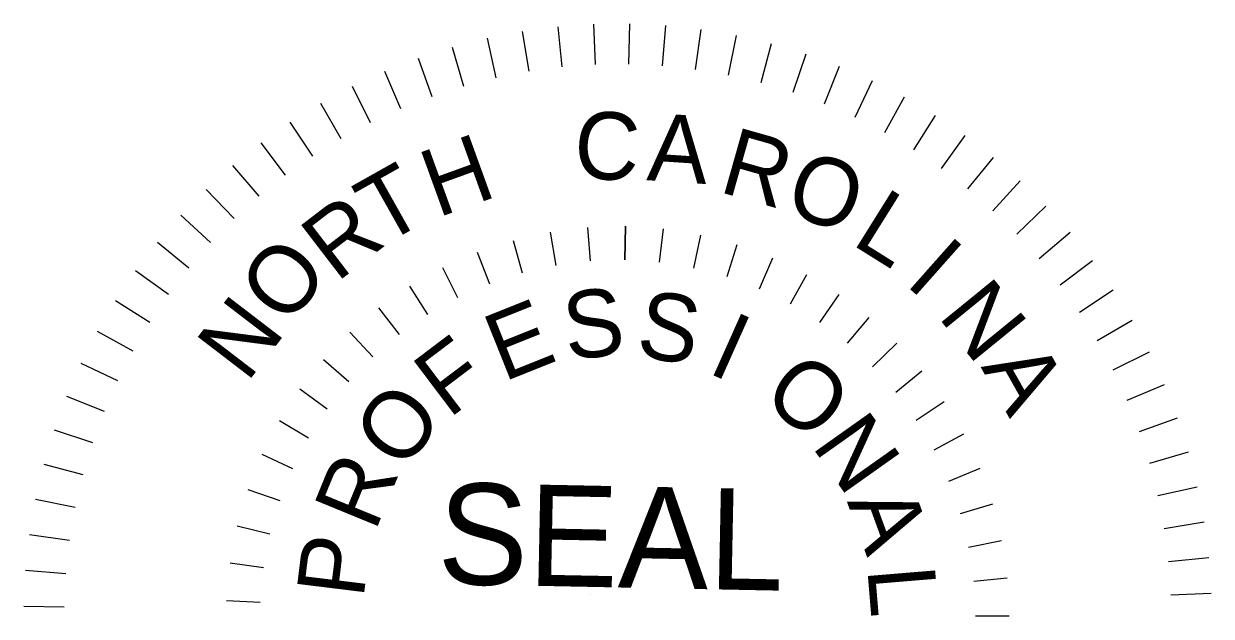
# Model space of a CAD drawing. Extents: x 0 to 2694, y -754 to 1499.
# Drawn here: x 3.6853 to 3.807, y 1.6046 to 1.6653 of the extents above; entities that cross this region are included whole.
import ezdxf

# ---------------------------------------------------------------- set-up
doc = ezdxf.new("R2010")
doc.units = 0
doc.layers.add('UBO Plan Sheet 34 CELL', color=7, linetype='Continuous')

msp = doc.modelspace()

# ---------------------------------------------------------------- linework, layer by layer
at = {"layer": 'UBO Plan Sheet 34 CELL'}
for p, q in [((3.73639, 1.66449), (3.73706, 1.6604)), ((3.74004, 1.66497), (3.74045, 1.66085)), ((3.7437, 1.66523), (3.74387, 1.66109)), ((3.74738, 1.66527), (3.7473, 1.66112)), ((3.75106, 1.66508), (3.75073, 1.66095)), ((3.75471, 1.66468), (3.75413, 1.66057)), ((3.73279, 1.66379), (3.73369, 1.65974)), ((3.75833, 1.66406), (3.7575, 1.65999)), ((3.72922, 1.66288), (3.73037, 1.65888)), ((3.76191, 1.66322), (3.76084, 1.65921)), ((3.76544, 1.66216), (3.76412, 1.65822)), ((3.72572, 1.66175), (3.72712, 1.65783)), ((3.76888, 1.66089), (3.76733, 1.65704)), ((3.7223, 1.6604), (3.72392, 1.65659)), ((3.71896, 1.65886), (3.72082, 1.65515)), ((3.77225, 1.65941), (3.77048, 1.65566)), ((3.77552, 1.65774), (3.77352, 1.6541)), ((3.71572, 1.65712), (3.7178, 1.65353)), ((3.7126, 1.65518), (3.71489, 1.65172)), ((3.77869, 1.65587), (3.77647, 1.65236)), ((3.78174, 1.65381), (3.77931, 1.65045)), ((3.7096, 1.65306), (3.71209, 1.64975)), ((3.78465, 1.65158), (3.78203, 1.64836)), ((3.70672, 1.65076), (3.70941, 1.64761)), ((3.78743, 1.64916), (3.78462, 1.64612)), ((3.704, 1.6483), (3.70687, 1.64531)), ((3.79006, 1.64659), (3.78707, 1.64372)), ((3.70143, 1.64567), (3.70447, 1.64286)), ((3.73925, 1.64393), (3.73984, 1.64052)), ((3.74309, 1.64441), (3.74336, 1.64097)), ((3.74697, 1.64452), (3.7469, 1.64107)), ((3.7469, 1.64107), (3.74697, 1.64452)), ((3.75084, 1.64426), (3.75044, 1.64083)), ((3.79252, 1.64387), (3.78937, 1.64118)), ((3.69901, 1.64289), (3.70223, 1.64027)), ((3.73547, 1.64308), (3.73639, 1.63974)), ((3.75466, 1.64362), (3.75393, 1.64024)), ((3.7584, 1.64262), (3.75735, 1.63933)), ((3.73179, 1.64186), (3.73303, 1.63863)), ((3.72824, 1.6403), (3.72978, 1.63721)), ((3.76204, 1.64127), (3.76067, 1.63809)), ((3.79483, 1.64099), (3.79151, 1.6385)), ((3.69678, 1.63998), (3.70014, 1.63755)), ((3.76552, 1.63956), (3.76386, 1.63653)), ((3.72486, 1.6384), (3.7267, 1.63547)), ((3.79694, 1.63799), (3.79349, 1.6357)), ((3.69472, 1.63693), (3.69823, 1.63471)), ((3.76882, 1.63753), (3.76687, 1.63467)), ((3.72168, 1.63618), (3.72379, 1.63344)), ((3.77191, 1.63519), (3.76969, 1.63253)), ((3.79888, 1.63487), (3.79529, 1.63279)), ((3.69285, 1.63376), (3.69649, 1.63176)), ((3.71873, 1.63367), (3.7211, 1.63115)), ((3.77476, 1.63256), (3.77229, 1.63013)), ((3.80062, 1.63163), (3.79691, 1.62977)), ((3.69118, 1.63049), (3.69493, 1.62871)), ((3.71603, 1.63089), (3.71863, 1.62861)), ((3.77734, 1.62967), (3.77466, 1.6275)), ((3.80216, 1.62829), (3.79835, 1.62667)), ((3.6897, 1.62712), (3.69355, 1.62557)), ((3.71362, 1.62786), (3.71642, 1.62583)), ((3.77964, 1.62655), (3.77675, 1.62463)), ((3.71151, 1.62461), (3.71449, 1.62286)), ((3.80351, 1.62487), (3.7996, 1.62347)), ((3.68843, 1.62367), (3.69237, 1.62236)), ((3.78161, 1.62322), (3.77856, 1.62159)), ((3.70972, 1.62116), (3.71286, 1.61972)), ((3.80464, 1.62137), (3.80065, 1.62022)), ((3.68737, 1.62015), (3.69138, 1.61908)), ((3.78327, 1.6197), (3.78007, 1.61839)), ((3.70828, 1.61756), (3.71155, 1.61643)), ((3.80555, 1.6178), (3.80151, 1.6169)), ((3.68653, 1.61657), (3.6906, 1.61574)), ((3.78457, 1.61605), (3.78125, 1.61505)), ((3.70718, 1.61385), (3.71054, 1.61303)), ((3.80625, 1.6142), (3.80216, 1.61353)), ((3.68591, 1.61295), (3.69002, 1.61237)), ((3.78551, 1.61229), (3.78212, 1.61162)), ((3.70646, 1.61004), (3.70988, 1.60956)), ((3.80673, 1.61055), (3.80261, 1.61014)), ((3.68551, 1.60929), (3.68964, 1.60896)), ((3.78609, 1.60846), (3.78265, 1.60812)), ((3.7061, 1.60618), (3.70955, 1.60602)), ((3.74334, 1.60681), (3.74334, 1.60681)), ((3.80699, 1.60689), (3.80285, 1.60672)), ((3.68532, 1.60562), (3.68947, 1.60554)), ((3.78629, 1.60459), (3.78284, 1.60457))]:
    msp.add_line(p, q, dxfattribs=at)

# ---------------------------------------------------------------- texts
for s, height, rotation, p in [('C', 0.00691, 356.2217, (3.74154, 1.64954)), ('A', 0.00691, 356.2217, (3.74909, 1.64925)), ('H', 0.00691, 19.9324, (3.72771, 1.64537)), ('R', 0.00691, 344.2124, (3.75639, 1.64809)), ('T', 0.00691, 29.3644, (3.72208, 1.64248)), ('O', 0.00691, 341.1556, (3.76304, 1.64597)), ('L', 0.00691, 328.0193, (3.77001, 1.64275)), ('R', 0.00691, 37.5253, (3.71736, 1.6387)), ('O', 0.00691, 50.5821, (3.71227, 1.63415)), ('I', 0.00691, 318.4439, (3.7755, 1.63863)), ('N', 0.00691, 309.1494, (3.77889, 1.63531)), ('S', 0.00691, 6.5129, (3.741, 1.63079)), ('S', 0.00691, 351.2166, (3.74791, 1.63123)), ('N', 0.00691, 52.5415, (3.70818, 1.62839)), ('E', 0.00691, 21.8091, (3.73446, 1.62855)), ('I', 0.00691, 335.9204, (3.75522, 1.62959)), ('F', 0.00691, 37.1054, (3.72886, 1.62475)), ('O', 0.00691, 320.6242, (3.76074, 1.62679)), ('A', 0.00691, 299.3819, (3.78335, 1.63012)), ('O', 0.00691, 52.4016, (3.72415, 1.61927)), ('N', 0.00691, 305.3279, (3.76597, 1.62206)), ('R', 0.00691, 67.6979, (3.7213, 1.61312)), ('SEAL', 0.010372, 358.8648, (3.72766, 1.60789)), ('A', 0.00691, 290.0317, (3.76965, 1.61633)), ('P', 0.00691, 82.9941, (3.72012, 1.60629)), ('L', 0.00691, 274.7354, (3.77175, 1.60945))]:
    msp.add_text(s, height=height, rotation=rotation, dxfattribs=at).set_placement(p)

doc.saveas('drawing.dxf')
